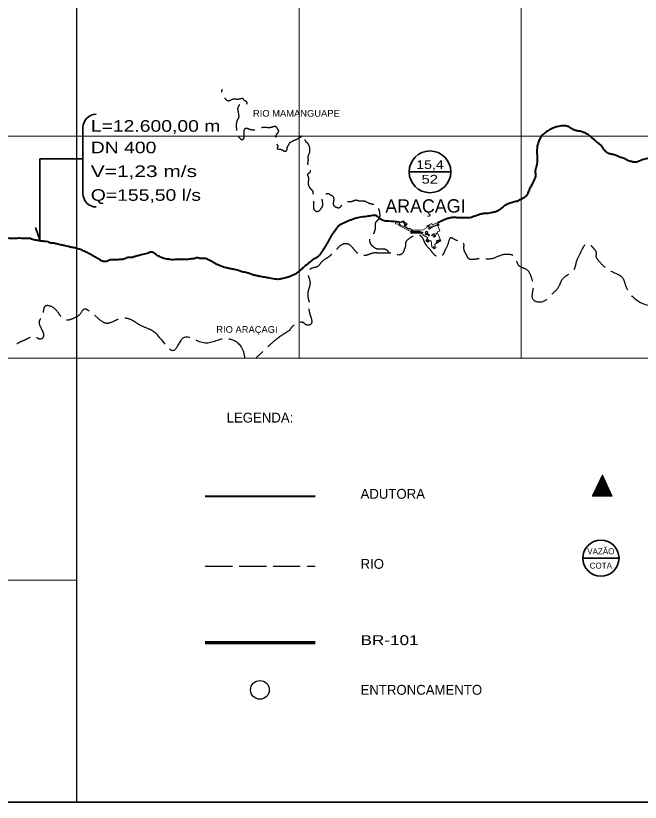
# Model space of a CAD drawing. Extents: x 0 to 1682, y 0 to 1188.
# Drawn here: x 1062.2 to 1241.3, y 427.1 to 652.9 of the extents above; entities that cross this region are included whole.
import ezdxf
from ezdxf.enums import TextEntityAlignment as Align

# ---------------------------------------------------------------- set-up
doc = ezdxf.new("R2010")
doc.units = 0
doc.header["$LTSCALE"] = 1.3
doc.linetypes.add('DOT_DASHED', pattern=[7.7, 5, -1.2, 0.3, -1.2])
doc.linetypes.add('LONG_DASHED', pattern=[7.5, 6, -1.5])
for name, color, linetype, lineweight in [('1', 7, 'DOT_DASHED', 13), ('4', 7, 'Continuous', 13), ('5', 7, 'LONG_DASHED', 25), ('6', 7, 'Continuous', 40), ('63', 7, 'Continuous', 25), ('8', 7, 'Continuous', 35), ('9', 7, 'Continuous', 40)]:
    doc.layers.add(name, color=color, linetype=linetype, lineweight=lineweight)

msp = doc.modelspace()

# ---------------------------------------------------------------- linework, layer by layer
at = {"layer": '1', "linetype": 'Continuous'}
for points in [[(1184.132, 588.291), (1183.103, 590.76), (1183.886, 591.087), (1183.25, 592.612), (1183.53, 592.729), (1183.441, 593.502), (1181.688, 592.821), (1181.509, 593.284), (1180.031, 592.469), (1180.243, 592.085), (1178.888, 591.338), (1175.714, 591.414), (1175.153, 591.933), (1174.857, 591.613), (1173.916, 592.484), (1174.355, 592.957), (1174.358, 593.379), (1173.937, 593.382), (1173.315, 593.955), (1172.352, 593.527), (1171.214, 593.621), (1171.171, 593.1), (1172.112, 593.023), (1172.084, 592.682), (1175.484, 590.969), (1175.505, 590.332), (1178.453, 590.43), (1179.19, 589.918), (1180.364, 589.103), (1179.809, 588.304), (1180.378, 587.908), (1181.027, 588.379), (1181.393, 588.283), (1181.591, 586.527), (1182.191, 585.988), (1182.769, 586.299), (1182.275, 587.217)], [(1172.309, 593.022), (1172.307, 593.378), (1173.244, 593.667), (1173.71, 593.224), (1174.214, 592.988), (1174.17, 592.895), (1173.722, 593.104), (1173.579, 592.798), (1174.286, 592.03), (1172.516, 592.805)], [(1180.455, 592.31), (1180.919, 592.591), (1180.821, 592.753), (1180.357, 592.472)], [(1183.322, 592.811), (1181.611, 592.18), (1180.789, 591.619), (1180.571, 591.939), (1181.118, 592.313), (1181.25, 592.12), (1181.602, 592.36), (1181.51, 592.494), (1181.902, 592.594), (1182.141, 592.501), (1183.269, 593.023)], [(1176.244, 590.909), (1175.879, 590.908), (1175.582, 591.065), (1175.665, 591.222), (1176.154, 591.205)], [(1175.692, 590.512), (1177.311, 590.517), (1177.311, 590.754), (1175.692, 590.749)], [(1178.178, 591.083), (1176.559, 591.078), (1176.56, 590.89), (1178.179, 590.895)], [(1177.578, 590.567), (1178.989, 590.571), (1178.989, 590.749), (1177.577, 590.745)], [(1180.108, 590.275), (1179.899, 589.997), (1179.621, 590.206), (1179.83, 590.484), (1179.679, 590.598), (1180.011, 591.039), (1180.358, 590.778), (1180.097, 590.431), (1180.864, 590.019), (1180.789, 589.607)], [(1182.201, 590.367), (1181.467, 589.772), (1182.021, 589.639), (1182.441, 589.995)], [(1182.586, 589.488), (1182.204, 589.276), (1182.058, 589.541), (1182.556, 589.817)], [(1182.718, 590.158), (1182.717, 590.372), (1182.931, 590.373), (1182.931, 590.159)], [(1180.229, 588.084), (1180.601, 588.458), (1180.419, 588.639), (1180.047, 588.265)], [(1183.164, 587.988), (1182.868, 587.738), (1182.759, 587.867), (1183.055, 588.117)], [(1182.934, 588.178), (1182.838, 588.369), (1183.029, 588.466), (1183.125, 588.274)], [(1183.927, 588.44), (1183.345, 588.16), (1183.267, 588.323), (1183.849, 588.602)], [(1182.165, 586.272), (1182.012, 586.444), (1182.259, 586.665), (1182.412, 586.493)]]:
    msp.add_lwpolyline(points, close=True, dxfattribs=at)
at = {"layer": '4'}
for p, q in [((1227.972, 515.828), (1231.368, 519.225)), ((1228.076, 516.046), (1231.334, 519.304)), ((1228.18, 516.263), (1231.299, 519.382)), ((1228.284, 516.48), (1231.264, 519.46)), ((1228.388, 516.697), (1231.229, 519.539)), ((1228.492, 516.914), (1231.194, 519.617)), ((1228.596, 517.132), (1231.16, 519.695)), ((1228.7, 517.349), (1231.125, 519.774)), ((1228.804, 517.566), (1231.09, 519.852)), ((1228.908, 517.783), (1231.055, 519.931)), ((1229.012, 518), (1231.021, 520.009)), ((1229.116, 518.218), (1230.986, 520.087)), ((1229.22, 518.435), (1230.951, 520.166)), ((1229.324, 518.652), (1230.916, 520.244)), ((1229.428, 518.869), (1230.882, 520.323)), ((1229.532, 519.086), (1230.847, 520.401)), ((1229.636, 519.303), (1230.812, 520.479)), ((1229.74, 519.521), (1230.777, 520.558)), ((1229.844, 519.738), (1230.743, 520.636)), ((1229.948, 519.955), (1230.708, 520.714)), ((1230.052, 520.172), (1230.673, 520.793)), ((1230.157, 520.389), (1230.638, 520.871)), ((1230.261, 520.607), (1230.604, 520.95)), ((1230.365, 520.824), (1230.569, 521.028)), ((1230.469, 521.041), (1230.534, 521.106)), ((1227.555, 514.96), (1231.507, 518.912)), ((1227.659, 515.177), (1231.473, 518.99)), ((1227.663, 514.954), (1231.542, 518.833)), ((1227.763, 515.394), (1231.438, 519.068)), ((1227.777, 514.955), (1231.577, 518.755)), ((1227.868, 515.611), (1231.403, 519.147)), ((1227.891, 514.956), (1231.612, 518.677)), ((1228.004, 514.956), (1231.646, 518.598)), ((1228.118, 514.957), (1231.681, 518.52)), ((1228.232, 514.957), (1231.716, 518.441)), ((1228.346, 514.958), (1231.751, 518.363)), ((1228.459, 514.959), (1231.785, 518.285)), ((1228.573, 514.959), (1231.82, 518.206)), ((1228.687, 514.96), (1231.855, 518.128)), ((1228.801, 514.96), (1231.89, 518.05)), ((1228.914, 514.961), (1231.924, 517.971)), ((1229.028, 514.962), (1231.959, 517.893)), ((1229.142, 514.962), (1231.994, 517.814)), ((1229.256, 514.963), (1232.029, 517.736)), ((1229.369, 514.963), (1232.063, 517.658)), ((1229.483, 514.964), (1232.098, 517.579)), ((1229.597, 514.965), (1232.133, 517.501)), ((1229.711, 514.965), (1232.168, 517.422)), ((1229.824, 514.966), (1232.202, 517.344)), ((1229.938, 514.966), (1232.237, 517.266)), ((1230.052, 514.967), (1232.272, 517.187)), ((1230.165, 514.968), (1232.307, 517.109)), ((1230.279, 514.968), (1232.342, 517.031)), ((1230.393, 514.969), (1232.376, 516.952)), ((1230.507, 514.97), (1232.411, 516.874)), ((1230.62, 514.97), (1232.446, 516.795)), ((1230.734, 514.971), (1232.481, 516.717)), ((1230.848, 514.971), (1232.515, 516.639)), ((1230.962, 514.972), (1232.55, 516.56)), ((1231.075, 514.973), (1232.585, 516.482)), ((1231.189, 514.973), (1232.62, 516.404)), ((1231.303, 514.974), (1232.654, 516.325)), ((1231.417, 514.974), (1232.689, 516.247)), ((1231.53, 514.975), (1232.724, 516.168)), ((1231.644, 514.976), (1232.759, 516.09)), ((1231.758, 514.976), (1232.793, 516.012)), ((1231.872, 514.977), (1232.828, 515.933)), ((1231.985, 514.977), (1232.863, 515.855)), ((1232.099, 514.978), (1232.898, 515.777)), ((1232.213, 514.979), (1232.932, 515.698)), ((1232.327, 514.979), (1232.967, 515.62)), ((1232.44, 514.98), (1233.002, 515.541)), ((1232.554, 514.98), (1233.037, 515.463)), ((1232.668, 514.981), (1233.071, 515.385)), ((1232.782, 514.982), (1233.106, 515.306)), ((1232.895, 514.982), (1233.141, 515.228)), ((1233.009, 514.983), (1233.176, 515.15)), ((1233.123, 514.983), (1233.21, 515.071)), ((1233.237, 514.984), (1233.245, 514.993))]:
    msp.add_line(p, q, dxfattribs=at)
at = {"layer": '4', "lineweight": 70}
msp.add_line((1116.522, 472.993), (1148.094, 472.993), dxfattribs=at)
at = {"layer": '4'}
msp.add_lwpolyline([(1227.553, 514.954), (1230.518, 521.143), (1233.249, 514.984)], close=True, dxfattribs=at)
at = {"layer": '4', "lineweight": 25}
msp.add_ellipse((1132.235, 459.392), major_axis=(2.687, 0), ratio=0.998913, dxfattribs=at)
at = {"layer": '5'}
msp.add_line((1116.522, 494.885), (1148.094, 494.885), dxfattribs=at)
for points in [[(1141.587, 616.809), (1140.988, 616.504), (1140.669, 616.338), (1140.511, 615.937), (1140.159, 615.399), (1140.022, 615.12), (1139.949, 614.541), (1139.802, 614.115), (1139.452, 613.866), (1139.067, 613.989), (1138.637, 614.298), (1138.092, 614.449), (1137.656, 614.448), (1137.35, 614.581), (1137.313, 614.955), (1137.445, 615.514), (1137.156, 615.917), (1136.895, 616.374), (1136.814, 617.188), (1136.812, 617.549), (1136.887, 618.38), (1137.166, 619.001), (1137.527, 619.475), (1137.624, 619.818), (1137.383, 620.274), (1137.047, 620.811), (1136.704, 621.051), (1135.979, 620.934), (1135.336, 620.761), (1134.176, 620.758), (1132.932, 620.754), (1132.275, 620.522), (1131.379, 620.25), (1130.899, 620.065), (1130.107, 620.063), (1129.591, 620.132), (1128.524, 620.488), (1127.947, 620.411), (1127.684, 620.064), (1127.613, 618.869), (1127.616, 617.885), (1127.4, 617.429), (1127.164, 617.198), (1126.708, 617.502), (1126.191, 618.023), (1125.918, 618.687), (1125.719, 619.542), (1125.56, 620.676), (1125.556, 621.823), (1125.635, 622.509), (1125.898, 623.107), (1126.228, 623.787), (1126.227, 624.223), (1126.069, 625.276), (1125.949, 626.388), (1126.2, 626.974), (1126.511, 627.443), (1127.173, 627.445), (1128.08, 627.448), (1128.498, 627.634), (1128.497, 628.07), (1127.901, 628.442), (1127.305, 629.065), (1126.224, 628.906), (1124.86, 628.902), (1124.061, 628.724), (1123.185, 628.38), (1122.59, 628.709), (1122.12, 629.435), (1121.633, 630.113), (1121.401, 630.647), (1121.397, 631.813)], [(1169.445, 584.729), (1168.844, 585.422), (1167.887, 585.886), (1165.91, 585.88), (1164.798, 586.544), (1164.218, 587.12), (1163.816, 587.853), (1163.814, 588.765), (1164.078, 589.455), (1164.676, 589.923), (1165.03, 590.681), (1165.382, 591.816), (1165.378, 593.128), (1165.797, 593.996), (1166.373, 594.598), (1166.638, 595.133), (1166.635, 596.156), (1166.365, 597.378), (1165.629, 598.399), (1164.428, 598.751), (1162.805, 599.369), (1161.982, 599.655), (1160.827, 599.652), (1159.849, 599.894), (1158.295, 599.466), (1157.473, 599.464), (1156.153, 598.713), (1155.407, 598.117), (1154.996, 597.704), (1154.159, 597.83), (1153.694, 598.099), (1153.357, 598.975), (1153.495, 600.136), (1153.235, 600.986), (1152.396, 601.435), (1151.958, 601.73), (1151.057, 601.573), (1150.581, 601.198), (1150.055, 600.657), (1150.057, 599.848), (1150.159, 599.075), (1150.161, 598.394), (1149.954, 597.875), (1149.592, 597.356), (1149.303, 596.937), (1148.968, 596.708), (1148.505, 596.616), (1148.141, 596.806), (1147.813, 597.241), (1147.72, 597.995), (1147.717, 598.959), (1147.715, 599.786), (1147.711, 600.995), (1147.619, 601.558), (1147.509, 601.894), (1147.507, 602.33), (1147.033, 602.929), (1146.551, 603.501), (1146.267, 604.163), (1146.129, 604.69), (1146.226, 605.681), (1146.224, 606.396), (1146.004, 606.979), (1146.08, 607.556), (1146.686, 607.981), (1146.683, 609.076), (1146.681, 609.788), (1146.11, 610.081), (1146.107, 611.247), (1146.103, 612.5), (1146.319, 613.126), (1146.546, 613.659), (1146.545, 614.247), (1146.543, 614.941), (1146.43, 615.337), (1146.274, 615.801), (1146.038, 616.122), (1145.715, 616.456), (1145.542, 616.573), (1145.353, 616.954), (1145.164, 617.367), (1145.029, 617.727), (1144.748, 618.054), (1144.671, 618.382), (1144.619, 618.605), (1144.273, 618.365), (1144.016, 618.071), (1143.359, 617.717), (1142.761, 617.343), (1142.117, 617.085), (1141.587, 616.809)], [(1451.442, 594.713), (1449.227, 590.884), (1446.563, 586.503), (1439.805, 584.791), (1428.258, 582.64), (1424.715, 589.542), (1422.876, 591.793), (1419.796, 585.154), (1414.598, 580.202), (1404.312, 580.171), (1404.299, 584.685), (1403.863, 584.684), (1401.614, 587.216), (1401.624, 583.972), (1397.678, 583.96), (1392.022, 590.996), (1389.49, 589.296), (1391.342, 582.672), (1391.359, 576.747), (1385.724, 576.731), (1378.954, 578.967), (1364.159, 578.923), (1359.238, 579.835), (1357.131, 582.312), (1354.117, 584.835), (1351.818, 587.742), (1349.761, 589.647), (1346.944, 590.355), (1343.364, 590.822), (1342.308, 592.634), (1341.346, 595.211), (1340.816, 597.263), (1340.812, 598.553), (1338.903, 598.547), (1337.042, 598.542), (1334.463, 599.537), (1332.455, 600.534), (1330.298, 599.807), (1328.344, 598.289), (1326.087, 595.636), (1324.371, 593.15), (1323.128, 590.69), (1321.788, 588.725), (1320.118, 587.019), (1315.053, 587.269), (1310.286, 587.255), (1306.249, 586.975), (1304.718, 586.629), (1301.513, 586.439), (1299.897, 587.469), (1298.89, 590.479), (1296.89, 592.452), (1294.985, 592.846), (1291.794, 591.447), (1287.927, 588.422), (1282.887, 587.238), (1279.09, 585.569), (1275.142, 584.239), (1271.683, 583.098), (1269.167, 581.131), (1266.953, 579.09), (1263.43, 576.475), (1256.037, 571.677), (1248.159, 569.455), (1241.668, 570.385), (1237.212, 575.318), (1236.458, 577.364), (1232.758, 579.601), (1231.058, 580.795), (1229.256, 582.749), (1228.74, 583.613), (1228.736, 584.911), (1228.112, 585.937), (1227.109, 586.962), (1225.892, 587.364), (1224.977, 586.469), (1223.929, 584.329), (1222.963, 582.189), (1222.482, 580.349), (1220.596, 578.531), (1218.737, 576.903), (1218.12, 575.413), (1215.736, 572.69), (1212.812, 570.647), (1210.683, 571.303), (1210.673, 574.851), (1210.097, 577.83), (1208.815, 579.955), (1206.637, 581.037), (1205.687, 582.832), (1204.596, 584.248)], [(1204.596, 584.248), (1201.807, 584.24), (1198.692, 583.095), (1194.769, 583.083), (1192.217, 583.076), (1191.362, 584.445), (1190.743, 586.052), (1190.739, 587.377), (1188.278, 588.552), (1186.974, 589.152), (1186.188, 587.427), (1185.241, 585.375), (1184.431, 583.976), (1183.641, 583.601), (1182.197, 584.342), (1180.983, 585.828), (1179.559, 587.617), (1178.67, 589.407), (1177.133, 589.985), (1175.252, 589.048), (1174, 587.717), (1174.003, 586.855), (1173.657, 585.783), (1173.311, 584.944), (1172.545, 584.29), (1169.788, 584.73), (1168.451, 584.726), (1166.504, 584.72), (1164.58, 584.715), (1162.987, 584.17), (1161.251, 584.165), (1160.006, 584.889), (1158.687, 586.435), (1157.582, 587.3), (1155.987, 587.296), (1154.583, 586.211), (1152.779, 584.337), (1151.304, 583.233), (1150.019, 582.299), (1148.791, 580.892), (1147.011, 580.336), (1146.048, 579.366), (1146.318, 577.564), (1146.607, 576.256), (1146.327, 574.757), (1145.99, 573.428), (1145.994, 572.062), (1146.262, 571.019), (1146.269, 568.534)], [(1100.519, 562.88), (1097.528, 564.254), (1095.533, 565.47), (1092.512, 566.072), (1090.138, 565.068), (1087.955, 564.612), (1085.766, 566.052), (1083.609, 567.814), (1081.968, 568.678), (1080.432, 567.033), (1078.62, 565.954), (1076.972, 565.509), (1075.539, 566.193), (1074.297, 567.758), (1072.065, 569.514), (1070.635, 569.509), (1070.116, 568.159), (1069.489, 566.34), (1068.915, 565.099), (1069.416, 563.256), (1070.08, 561.799), (1070.083, 560.753), (1069.48, 560.063), (1069.045, 560.062), (1068.049, 560.554), (1066.399, 560.549), (1065.026, 559.885), (1063.186, 559.081), (1062.527, 558.693)], [(1146.269, 568.534), (1146.495, 567.45), (1147.061, 565.516), (1146.924, 564.446), (1145.488, 564.162), (1144.659, 564.809), (1143.603, 564.805), (1142.18, 564.203), (1141.216, 563.308), (1140.697, 562.517)], [(1127.992, 554.567), (1126.81, 557.959), (1122.256, 560.179), (1116.083, 558.958), (1110.245, 560.4), (1107.682, 556.872), (1101.919, 562.093), (1100.304, 562.979)], [(1140.697, 562.517), (1136.67, 559.792), (1134.189, 557.552), (1131.015, 554.567)]]:
    msp.add_spline(points, degree=3, dxfattribs=at)
at = {"layer": '6'}
for p, q in [((1172.2, 593.643), (1172.352, 593.527)), ((1116.522, 514.984), (1148.094, 514.984))]:
    msp.add_line(p, q, dxfattribs=at)
for points in [[(1232.13, 613.45), (1231.595, 613.77), (1230.797, 614.574), (1230.018, 615.671), (1229.146, 616.415), (1228.306, 617.166), (1227.659, 617.651), (1226.836, 618.374), (1225.839, 619.066), (1225.441, 619.237), (1224.658, 619.524), (1223.97, 619.699), (1223.139, 619.821), (1222.317, 620.131), (1221.65, 620.454), (1221.062, 620.913), (1220.54, 621.106), (1219.177, 621.285), (1217.444, 621.008), (1216.585, 620.734), (1215.37, 620.175), (1214.363, 619.536), (1213.433, 618.768), (1212.686, 617.817), (1212.176, 616.651), (1211.72, 614.918), (1211.732, 610.637), (1211.529, 609.755), (1211.351, 609.04), (1211.225, 608.512), (1211.227, 607.827), (1211.319, 607.432), (1211.32, 607.075), (1211.255, 606.784), (1211.162, 606.35), (1211.045, 606.04), (1210.821, 605.613), (1210.426, 604.856), (1210.142, 604.226), (1209.897, 603.731), (1209.598, 603.149), (1209.333, 602.544), (1209.107, 601.987), (1208.985, 601.625), (1208.835, 601.423), (1208.699, 601.203), (1208.565, 601.08), (1208.339, 600.906), (1208.16, 600.703), (1207.78, 600.499), (1207.472, 600.295), (1207.144, 600.151), (1207.045, 600.073), (1207.02, 600.072), (1206.232, 599.661), (1205.585, 599.506), (1204.982, 599.354), (1204.337, 599.187), (1203.736, 599.004), (1203.157, 598.784), (1202.57, 598.457), (1202.121, 598.115), (1201.67, 597.727), (1201.33, 597.435), (1200.946, 597.158), (1200.534, 596.877), (1200.124, 596.67), (1199.772, 596.575), (1198.849, 596.379), (1198.032, 596.213), (1197.234, 596.115), (1196.344, 596.113), (1195.775, 595.951), (1195.252, 595.788), (1194.771, 595.642), (1194.22, 595.45), (1193.688, 595.277), (1192.892, 594.984), (1191.982, 594.845), (1190.839, 594.842), (1189.823, 594.839), (1189.313, 594.837), (1189.033, 594.836), (1188.394, 594.977), (1187.778, 594.975), (1186.526, 594.764), (1185.618, 594.467), (1185.085, 594.254), (1184.288, 593.923), (1183.073, 593.363)], [(1274.077, 612.218), (1273.439, 611.867), (1272.986, 611.633), (1272.577, 611.457), (1272.037, 611.456), (1271.194, 611.599), (1270.398, 611.88), (1269.973, 612.106), (1269.258, 612.537), (1268.232, 612.934), (1266.927, 612.93), (1266.124, 612.488), (1265.234, 612.485), (1264.238, 612.357), (1263.241, 612.482), (1262.124, 612.801), (1261.514, 612.8), (1260.303, 612.796), (1258.917, 612.792), (1257.858, 612.986), (1256.832, 613.183), (1256.445, 613.364), (1255.881, 613.625), (1254.852, 613.622), (1253.238, 613.291), (1251.751, 613.059), (1250.433, 612.878), (1248.488, 613.029), (1246.976, 612.886), (1244.746, 612.13), (1243.778, 611.909), (1242.301, 611.629), (1240.652, 610.991), (1240.004, 610.802), (1239.083, 610.926), (1237.934, 611.232), (1237.05, 611.764), (1235.784, 612.221), (1234.648, 612.647), (1233.58, 613), (1232.595, 613.24), (1232.019, 613.469)], [(1172.2, 593.643), (1169.171, 593.877), (1167.549, 594.122), (1167.1, 594.313), (1166.281, 594.961), (1165.468, 595.5), (1164.437, 595.497), (1162.824, 595.261), (1160.666, 594.936), (1159.05, 594.509), (1156.865, 593.65), (1155.283, 592.863), (1154.492, 592.259), (1153.962, 591.523), (1153.667, 591.019), (1153.347, 590.588), (1152.84, 589.98), (1152.42, 589.153), (1152.002, 588.467), (1151.578, 587.716), (1151.127, 586.904), (1150.664, 586.126), (1150.249, 585.485), (1149.708, 584.685), (1149.202, 584.042), (1148.851, 583.707), (1148.425, 583.421), (1147.644, 582.976), (1146.896, 582.426), (1146.141, 581.813), (1145.609, 581.391), (1144.937, 580.806), (1144.319, 580.252), (1143.724, 579.707), (1143.03, 579.154), (1142.158, 578.603), (1141.307, 578.184), (1140.423, 577.866), (1139.55, 577.612), (1138.81, 577.437), (1137.78, 577.22), (1136.93, 577.217), (1135.088, 577.527), (1133.62, 577.801), (1132.171, 578.059), (1131.162, 578.27), (1130.165, 578.487), (1129.19, 578.859), (1128.262, 579.155), (1127.462, 579.309), (1126.705, 579.53)], [(1126.716, 579.526), (1124.889, 580.049), (1123.647, 580.271), (1122.606, 580.519), (1121.797, 580.75), (1121.042, 580.994), (1120.266, 581.327), (1119.486, 581.689), (1118.583, 582.275), (1117.64, 582.744), (1116.765, 583.134), (1115.689, 583.21), (1114.922, 583.207), (1114.416, 583.402), (1113.554, 583.198), (1112.303, 583.02), (1111.535, 582.909), (1110.519, 582.906), (1108.421, 582.9), (1106.499, 582.894), (1105.969, 582.979), (1105.084, 583.089), (1104.378, 583.325), (1103.629, 583.613), (1103.194, 583.832), (1102.689, 584.132), (1102.274, 584.477), (1101.552, 584.897), (1100.458, 584.894), (1099.896, 584.635), (1099.029, 584.442), (1098.211, 584.252), (1097.64, 584.081), (1097.112, 583.98), (1096.547, 583.811), (1096.097, 583.64), (1095.748, 583.52), (1095.355, 583.449), (1094.328, 583.446), (1093.674, 583.215), (1093.144, 583.033), (1092.527, 582.894), (1091.835, 582.892), (1091.193, 582.788), (1090.598, 582.786), (1090.159, 582.785), (1089.353, 582.782), (1088.725, 582.523), (1088.267, 582.34), (1087.656, 582.338), (1087.056, 582.414), (1086.54, 582.687), (1085.682, 583.222), (1084.562, 583.862), (1083.633, 584.413), (1082.414, 585.019), (1081.257, 585.54), (1080.245, 585.916), (1079.133, 586.215), (1078.02, 586.405), (1077.185, 586.651), (1076.355, 586.833), (1075.384, 587.055), (1074.589, 587.233), (1073.691, 587.428), (1072.627, 587.618), (1072.225, 587.617), (1071.937, 587.719), (1071.372, 587.951), (1070.463, 588.082), (1069.404, 588.208), (1068.417, 588.354), (1067.766, 588.466), (1067.066, 588.632), (1066.356, 588.899), (1065.485, 588.896), (1063.966, 588.972), (1062.086, 588.967), (1061.337, 588.965), (1057.275, 588.952), (1055.259, 588.814), (1052.322, 588.805), (1048.698, 588.794), (1046.791, 588.956), (1045.01, 589.096)]]:
    msp.add_spline(points, degree=3, dxfattribs=at)
at = {"layer": '63'}
msp.add_line((1079.738, 427.142), (1079.738, 783.93), dxfattribs=at)
at = {"layer": '63', "lineweight": 13}
for p, q in [((1143.45, 554.567), (1143.45, 783.93)), ((1207.162, 554.567), (1207.162, 783.93)), ((1640.404, 618.279), (952.314, 618.279)), ((1640.404, 554.567), (952.314, 554.567)), ((1079.738, 490.855), (952.314, 490.855))]:
    msp.add_line(p, q, dxfattribs=at)
at = {"layer": '63', "lineweight": 35}
msp.add_lwpolyline([(1640.404, 427.142), (952.314, 427.142), (952.314, 783.93)], dxfattribs=at)
at = {"layer": '8'}
msp.add_line((1081.468, 601.81), (1081.468, 620.766), dxfattribs=at)
msp.add_lwpolyline([(1081.468, 611.767), (1069.118, 611.767), (1069.118, 588.531), (1067.852, 592.097)], dxfattribs=at)
for centre, start, end in [((1085.29, 620.766), 90, 180), ((1085.29, 620.766), 90, 180), ((1085.29, 620.766), 90, 180), ((1085.29, 601.81), 180, 270)]:
    msp.add_arc(centre, 3.823, start, end, dxfattribs=at)
at = {"layer": '9', "lineweight": 35}
for p, q in [((1175.027, 608.058), (1186.998, 608.058)), ((1224.883, 497.205), (1235.247, 497.205))]:
    msp.add_line(p, q, dxfattribs=at)
for centre, radius in [((1181.012, 608.058), 5.985), ((1230.065, 497.205), 5.182)]:
    msp.add_circle(centre, radius, dxfattribs=at)

# ---------------------------------------------------------------- texts
at = {"layer": '5', "width": 1.05}
for s, rotation, p in [('RIO MAMANGUAPE', 0.006, (1130.242, 623.889)), ('RIO ARAÇAGI', 359.911, (1119.708, 561.886))]:
    msp.add_text(s, height=1.911, rotation=rotation, dxfattribs=at).set_placement(p)
at = {"layer": '63'}
for s, p in [('LEGENDA:', (1122.683, 536.115)), ('ADUTORA', (1161.095, 514.245)), ('RIO', (1161.095, 494.146)), ('ENTRONCAMENTO', (1161.095, 458))]:
    msp.add_text(s, height=2.829, dxfattribs=at).set_placement(p)
at = {"layer": '63', "width": 1.3}
msp.add_text('BR-101', height=2.829, dxfattribs=at).set_placement((1161.095, 472.254))
at = {"layer": '8'}
for s, width, p in [('L=12.600,00 m', 1.25, (1083.719, 619.574)), ('DN 400', 1.25, (1083.719, 613.394)), ('V=1,23 m/s', 1.35, (1083.719, 606.571)), ('Q=155,50 l/s', 1.25, (1083.719, 599.747))]:
    msp.add_text(s, height=3.319, dxfattribs=dict(at, width=width)).set_placement(p)
at = {"layer": '9'}
for s, width, p in [('15,4', 1.2, (1181.022, 608.878)), ('52', 1.25, (1180.948, 604.675))]:
    msp.add_text(s, height=2.52, rotation=0.17, dxfattribs=dict(at, width=width)).set_placement(p, align=Align.CENTER)
msp.add_text('ARAÇAGI', height=3.823, rotation=0.17, dxfattribs=at).set_placement((1168.207, 596.32))
for s, p in [('VAZÃO', (1230.033, 498.305)), ('COTA', (1230.033, 494.204))]:
    msp.add_text(s, height=1.72, rotation=0.17, dxfattribs=at).set_placement(p, align=Align.CENTER)

doc.saveas('drawing.dxf')
